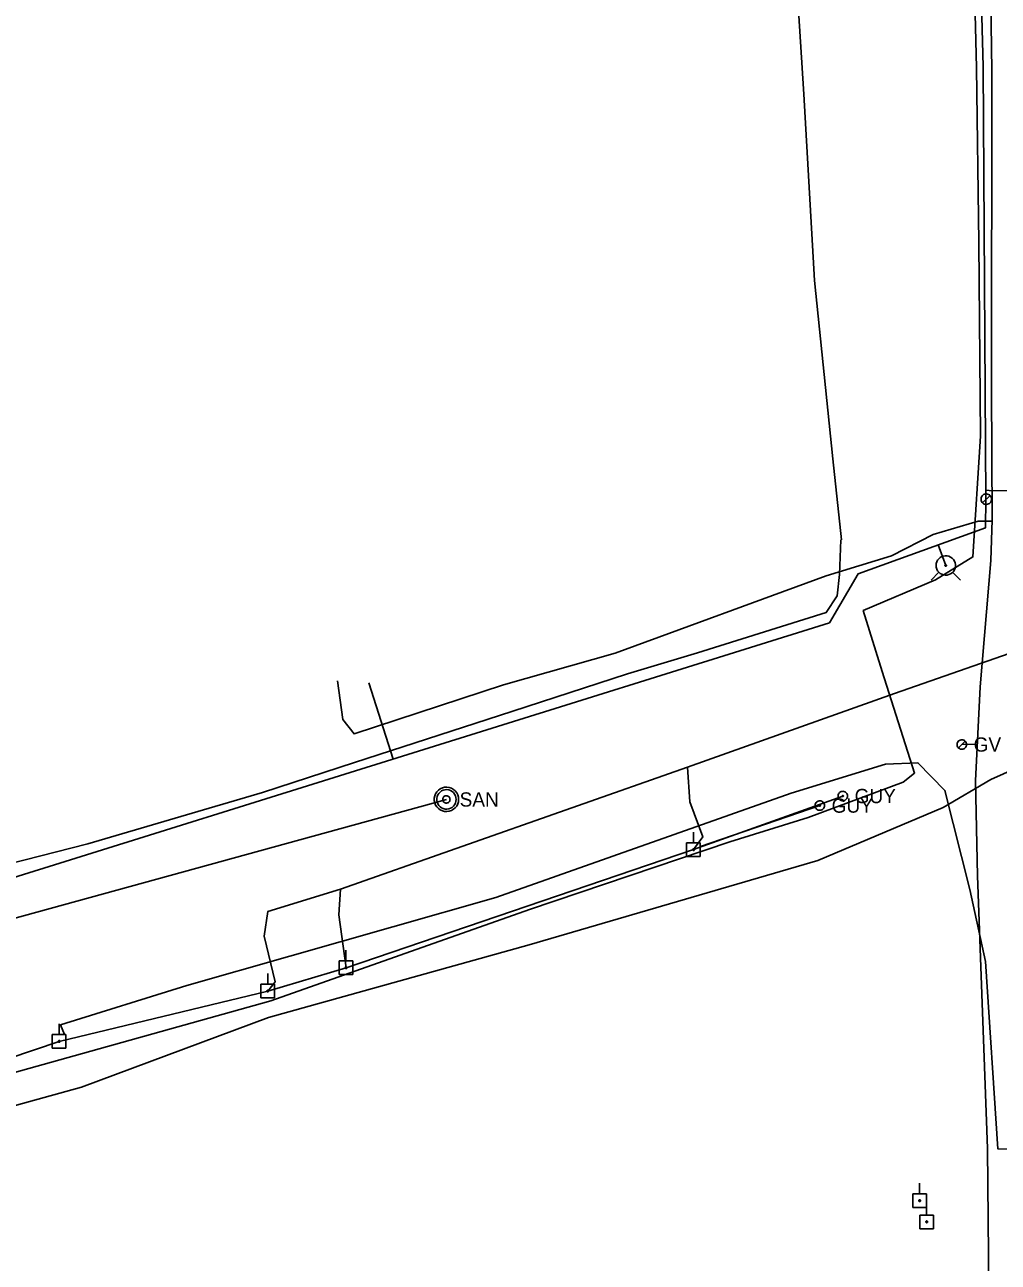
# Model space of a CAD drawing. Extents: x 600849 to 606371, y 330010 to 403088.
# Drawn here: x 604586.8 to 604850, y 333639.5 to 333973.9 of the extents above; entities that cross this region are included whole.
import ezdxf

# ---------------------------------------------------------------- set-up
doc = ezdxf.new("R2010")
doc.units = 0
for name, color, linetype in [('E_UTL_E_UG', 7, 'Continuous'), ('E_UTL_EGuyWire', 7, 'Continuous'), ('E_UTL_EPowerPole', 7, 'Continuous'), ('E_UTL_FO_UG_QWEST', 7, 'Continuous'), ('E_UTL_G', 7, 'Continuous'), ('E_UTL_G_UG', 7, 'Continuous'), ('E_UTL_Overhead', 7, 'Continuous'), ('E_UTL_SAN', 7, 'Continuous'), ('E_UTL_SAN_UG', 7, 'Continuous'), ('E_UTL_T_UG', 7, 'Continuous'), ('E_UTL_W', 7, 'Continuous'), ('E_UTL_W_UG', 7, 'Continuous'), ('E_UTL_WHydrant', 7, 'Continuous')]:
    doc.layers.add(name, color=color, linetype=linetype)

msp = doc.modelspace()

# ---------------------------------------------------------------- linework, layer by layer
at = {"layer": 'E_UTL_E_UG'}
msp.add_line((604671.71, 333733.36), (604673.7, 333719.09), dxfattribs=at)
for points in [[(604807.59, 333834.76), (604805.26, 333856.62), (604800.37, 333904.78), (604797.43, 333955.12), (604794.17, 334006.19), (604805.24, 334046.05)], [(604440.14, 333718.83), (604480.42, 333725.03), (604538.85, 333736.02), (604603.87, 333752.62), (604651.09, 333766.43), (604675.97, 333774.58), (604718.55, 333788.33), (604749.73, 333798.5), (604768.73, 333804.21), (604803.48, 333815.07), (604806.49, 333819.63), (604807.09, 333825.4), (604807.44, 333834.72)], [(604767.62, 333751), (604770.14, 333754.43), (604766.59, 333763.96), (604765.98, 333773.32), (604821.96, 333793.21), (604872.29, 333810.74)], [(604597.6, 333701.08), (604596.5, 333703.7), (604630.64, 333714.29), (604714.18, 333738.06), (604794.04, 333766.23), (604819.54, 333774.15), (604828.3, 333774.47), (604835.57, 333767), (604842.31, 333740.21), (604846.52, 333720.82)], [(604652.54, 333712.8), (604654.49, 333715.25), (604651.55, 333727.64), (604652.56, 333734.31), (604672.23, 333740.35), (604765.98, 333773.32)], [(604672.23, 333740.35), (604671.71, 333733.36)], [(604846.52, 333720.82), (604849.87, 333670.16), (604892.6, 333668.93), (604894.5, 333662.83)]]:
    msp.add_lwpolyline(points, dxfattribs=at)
at = {"layer": 'E_UTL_EGuyWire'}
for p, q in [((604807.96, 333765.49), (604767.62, 333751)), ((604801.75, 333762.91), (604769.53, 333751.88))]:
    msp.add_line(p, q, dxfattribs=at)
for points in [[(604809.24, 333765.49), (604809.22, 333765.74), (604809.15, 333765.97), (604809.04, 333766.19), (604808.89, 333766.38), (604808.7, 333766.54), (604808.49, 333766.66), (604808.26, 333766.74), (604808.02, 333766.77), (604807.78, 333766.76), (604807.54, 333766.71), (604807.32, 333766.6), (604807.12, 333766.46), (604806.95, 333766.29), (604806.82, 333766.08), (604806.73, 333765.85), (604806.68, 333765.61), (604806.68, 333765.37), (604806.73, 333765.13), (604806.82, 333764.9), (604806.95, 333764.7), (604807.12, 333764.52), (604807.32, 333764.38), (604807.54, 333764.28), (604807.78, 333764.22), (604808.02, 333764.21), (604808.26, 333764.25), (604808.49, 333764.33), (604808.7, 333764.45), (604808.89, 333764.61), (604809.04, 333764.8), (604809.15, 333765.02), (604809.22, 333765.25), (604809.24, 333765.49)], [(604808.12, 333765.49), (604808.12, 333765.52), (604808.11, 333765.55), (604808.1, 333765.58), (604808.08, 333765.6), (604808.05, 333765.62), (604808.03, 333765.64), (604808, 333765.65), (604807.97, 333765.65), (604807.94, 333765.65), (604807.91, 333765.64), (604807.88, 333765.63), (604807.86, 333765.61), (604807.83, 333765.59), (604807.82, 333765.57), (604807.81, 333765.54), (604807.8, 333765.51), (604807.8, 333765.48), (604807.81, 333765.45), (604807.82, 333765.42), (604807.83, 333765.39), (604807.86, 333765.37), (604807.88, 333765.35), (604807.91, 333765.34), (604807.94, 333765.33), (604807.97, 333765.33), (604808, 333765.34), (604808.03, 333765.35), (604808.05, 333765.36), (604808.08, 333765.38), (604808.1, 333765.41), (604808.11, 333765.43), (604808.12, 333765.46), (604808.12, 333765.49)], [(604803.03, 333762.91), (604803.01, 333763.16), (604802.94, 333763.39), (604802.83, 333763.61), (604802.68, 333763.8), (604802.49, 333763.96), (604802.28, 333764.08), (604802.05, 333764.16), (604801.81, 333764.19), (604801.57, 333764.18), (604801.33, 333764.13), (604801.11, 333764.02), (604800.91, 333763.88), (604800.74, 333763.71), (604800.61, 333763.5), (604800.52, 333763.27), (604800.47, 333763.03), (604800.47, 333762.79), (604800.52, 333762.55), (604800.61, 333762.32), (604800.74, 333762.12), (604800.91, 333761.94), (604801.11, 333761.8), (604801.33, 333761.7), (604801.57, 333761.64), (604801.81, 333761.63), (604802.05, 333761.67), (604802.28, 333761.75), (604802.49, 333761.87), (604802.68, 333762.03), (604802.83, 333762.22), (604802.94, 333762.44), (604803.01, 333762.67), (604803.03, 333762.91)], [(604801.91, 333762.91), (604801.91, 333762.94), (604801.9, 333762.97), (604801.89, 333763), (604801.87, 333763.02), (604801.84, 333763.04), (604801.82, 333763.06), (604801.79, 333763.07), (604801.76, 333763.07), (604801.73, 333763.07), (604801.7, 333763.06), (604801.67, 333763.05), (604801.65, 333763.03), (604801.62, 333763.01), (604801.61, 333762.99), (604801.6, 333762.96), (604801.59, 333762.93), (604801.59, 333762.9), (604801.6, 333762.87), (604801.61, 333762.84), (604801.62, 333762.81), (604801.65, 333762.79), (604801.67, 333762.77), (604801.7, 333762.76), (604801.73, 333762.75), (604801.76, 333762.75), (604801.79, 333762.76), (604801.82, 333762.77), (604801.84, 333762.78), (604801.87, 333762.8), (604801.89, 333762.83), (604801.9, 333762.85), (604801.91, 333762.88), (604801.91, 333762.91)]]:
    msp.add_lwpolyline(points, dxfattribs=at)
at = {"layer": 'E_UTL_EPowerPole'}
for points in [[(604767.59, 333752.84), (604767.59, 333755.75)], [(604769.43, 333752.84), (604765.74, 333752.84)], [(604765.74, 333752.84), (604765.74, 333749.15)], [(604769.43, 333749.15), (604769.43, 333752.84)], [(604765.74, 333749.15), (604769.43, 333749.15)], [(604767.86, 333751), (604767.85, 333751.04), (604767.84, 333751.09), (604767.82, 333751.13), (604767.79, 333751.16), (604767.76, 333751.19), (604767.72, 333751.22), (604767.68, 333751.23), (604767.63, 333751.24), (604767.59, 333751.24), (604767.54, 333751.22), (604767.5, 333751.21), (604767.46, 333751.18), (604767.43, 333751.15), (604767.41, 333751.11), (604767.39, 333751.07), (604767.38, 333751.02), (604767.38, 333750.98), (604767.39, 333750.93), (604767.41, 333750.89), (604767.43, 333750.85), (604767.46, 333750.82), (604767.5, 333750.79), (604767.54, 333750.77), (604767.59, 333750.76), (604767.63, 333750.76), (604767.68, 333750.77), (604767.72, 333750.78), (604767.76, 333750.81), (604767.79, 333750.83), (604767.82, 333750.87), (604767.84, 333750.91), (604767.85, 333750.95), (604767.86, 333751)], [(604673.66, 333720.93), (604673.66, 333723.84)], [(604675.51, 333720.93), (604671.82, 333720.93)], [(604671.82, 333720.93), (604671.82, 333717.24)], [(604673.94, 333719.09), (604673.93, 333719.14), (604673.92, 333719.18), (604673.9, 333719.22), (604673.87, 333719.25), (604673.84, 333719.28), (604673.8, 333719.31), (604673.75, 333719.32), (604673.71, 333719.33), (604673.66, 333719.33), (604673.62, 333719.32), (604673.58, 333719.3), (604673.54, 333719.27), (604673.51, 333719.24), (604673.48, 333719.2), (604673.47, 333719.16), (604673.46, 333719.11), (604673.46, 333719.07), (604673.47, 333719.02), (604673.48, 333718.98), (604673.51, 333718.94), (604673.54, 333718.91), (604673.58, 333718.88), (604673.62, 333718.87), (604673.66, 333718.85), (604673.71, 333718.85), (604673.75, 333718.86), (604673.8, 333718.87), (604673.84, 333718.9), (604673.87, 333718.93), (604673.9, 333718.96), (604673.92, 333719), (604673.93, 333719.05), (604673.94, 333719.09)], [(604675.51, 333717.24), (604675.51, 333720.93)], [(604652.51, 333714.65), (604652.51, 333717.56)], [(604671.82, 333717.24), (604675.51, 333717.24)], [(604654.35, 333714.65), (604650.66, 333714.65)], [(604650.66, 333714.65), (604650.66, 333710.96)], [(604652.78, 333712.8), (604652.77, 333712.85), (604652.76, 333712.89), (604652.74, 333712.93), (604652.71, 333712.97), (604652.68, 333713), (604652.64, 333713.02), (604652.59, 333713.04), (604652.55, 333713.04), (604652.5, 333713.04), (604652.46, 333713.03), (604652.42, 333713.01), (604652.38, 333712.98), (604652.35, 333712.95), (604652.33, 333712.91), (604652.31, 333712.87), (604652.3, 333712.83), (604652.3, 333712.78), (604652.31, 333712.74), (604652.33, 333712.7), (604652.35, 333712.66), (604652.38, 333712.62), (604652.42, 333712.6), (604652.46, 333712.58), (604652.5, 333712.57), (604652.55, 333712.57), (604652.59, 333712.57), (604652.64, 333712.59), (604652.68, 333712.61), (604652.71, 333712.64), (604652.74, 333712.68), (604652.76, 333712.72), (604652.77, 333712.76), (604652.78, 333712.8)], [(604654.35, 333710.96), (604654.35, 333714.65)], [(604650.66, 333710.96), (604654.35, 333710.96)], [(604596.1, 333701.04), (604596.1, 333703.94)], [(604597.95, 333701.04), (604594.26, 333701.04)], [(604594.26, 333701.04), (604594.26, 333697.34)], [(604596.38, 333699.19), (604596.37, 333699.24), (604596.36, 333699.28), (604596.34, 333699.32), (604596.31, 333699.36), (604596.28, 333699.39), (604596.24, 333699.41), (604596.19, 333699.42), (604596.15, 333699.43), (604596.1, 333699.43), (604596.06, 333699.42), (604596.02, 333699.4), (604595.98, 333699.37), (604595.95, 333699.34), (604595.92, 333699.3), (604595.91, 333699.26), (604595.9, 333699.22), (604595.9, 333699.17), (604595.91, 333699.13), (604595.92, 333699.08), (604595.95, 333699.05), (604595.98, 333699.01), (604596.02, 333698.99), (604596.06, 333698.97), (604596.1, 333698.96), (604596.15, 333698.95), (604596.19, 333698.96), (604596.24, 333698.98), (604596.28, 333699), (604596.31, 333699.03), (604596.34, 333699.06), (604596.36, 333699.1), (604596.37, 333699.15), (604596.38, 333699.19)], [(604597.95, 333697.34), (604597.95, 333701.04)], [(604594.26, 333697.34), (604597.95, 333697.34)], [(604830.56, 333657.97), (604826.87, 333657.97)], [(604826.87, 333657.97), (604826.87, 333654.27)], [(604828.72, 333657.97), (604828.72, 333660.87)], [(604830.56, 333654.27), (604830.56, 333657.97)], [(604828.99, 333656.12), (604828.98, 333656.17), (604828.97, 333656.21), (604828.95, 333656.25), (604828.92, 333656.29), (604828.89, 333656.32), (604828.85, 333656.34), (604828.81, 333656.35), (604828.76, 333656.36), (604828.72, 333656.36), (604828.67, 333656.35), (604828.63, 333656.33), (604828.59, 333656.3), (604828.56, 333656.27), (604828.54, 333656.23), (604828.52, 333656.19), (604828.51, 333656.15), (604828.51, 333656.1), (604828.52, 333656.06), (604828.54, 333656.01), (604828.56, 333655.98), (604828.59, 333655.94), (604828.63, 333655.92), (604828.67, 333655.9), (604828.72, 333655.89), (604828.76, 333655.88), (604828.81, 333655.89), (604828.85, 333655.91), (604828.89, 333655.93), (604828.92, 333655.96), (604828.95, 333655.99), (604828.97, 333656.03), (604828.98, 333656.08), (604828.99, 333656.12)], [(604830.64, 333652.27), (604830.64, 333655.17)], [(604826.87, 333654.27), (604830.56, 333654.27)], [(604832.48, 333652.27), (604828.79, 333652.27)], [(604828.79, 333652.27), (604828.79, 333648.57)], [(604832.48, 333648.57), (604832.48, 333652.27)], [(604828.79, 333648.57), (604832.48, 333648.57)], [(604830.91, 333650.42), (604830.9, 333650.47), (604830.89, 333650.51), (604830.87, 333650.55), (604830.84, 333650.59), (604830.81, 333650.62), (604830.77, 333650.64), (604830.73, 333650.65), (604830.68, 333650.66), (604830.64, 333650.66), (604830.59, 333650.65), (604830.55, 333650.63), (604830.51, 333650.6), (604830.48, 333650.57), (604830.46, 333650.53), (604830.44, 333650.49), (604830.43, 333650.45), (604830.43, 333650.4), (604830.44, 333650.36), (604830.46, 333650.31), (604830.48, 333650.28), (604830.51, 333650.24), (604830.55, 333650.22), (604830.59, 333650.2), (604830.64, 333650.19), (604830.68, 333650.18), (604830.73, 333650.19), (604830.77, 333650.21), (604830.81, 333650.23), (604830.84, 333650.26), (604830.87, 333650.29), (604830.89, 333650.33), (604830.9, 333650.38), (604830.91, 333650.42)]]:
    msp.add_lwpolyline(points, dxfattribs=at)
at = {"layer": 'E_UTL_FO_UG_QWEST'}
msp.add_lwpolyline([(604064.36, 333597.95), (604125.52, 333607.24), (604222.69, 333622.89), (604294.58, 333635.82), (604348.76, 333642.01), (604429.81, 333649.86), (604519.71, 333664), (604602.19, 333686.85), (604652.71, 333705.68), (604723.21, 333725.29), (604801.25, 333748.09), (604835.09, 333762.42), (604848.03, 333769.94), (604883.85, 333785.99), (604890.17, 333789.47), (604890.94, 333790.11), (604892.16, 333796.08), (604892.06, 333804.65), (604893.55, 333818.96), (604893.11, 333877.27), (604889.73, 333952.96), (604886.58, 334030.08), (604884.67, 334105.68), (604880.28, 334183.13)], dxfattribs=at)
at = {"layer": 'E_UTL_G'}
for points in [[(604841.41, 333779.41), (604841.39, 333779.66), (604841.32, 333779.89), (604841.21, 333780.11), (604841.06, 333780.3), (604840.87, 333780.46), (604840.66, 333780.58), (604840.43, 333780.66), (604840.19, 333780.69), (604839.95, 333780.68), (604839.71, 333780.63), (604839.49, 333780.52), (604839.29, 333780.38), (604839.12, 333780.21), (604838.99, 333780), (604838.9, 333779.77), (604838.85, 333779.53), (604838.85, 333779.29), (604838.9, 333779.05), (604838.99, 333778.82), (604839.12, 333778.62), (604839.29, 333778.44), (604839.49, 333778.3), (604839.71, 333778.2), (604839.95, 333778.14), (604840.19, 333778.13), (604840.43, 333778.17), (604840.66, 333778.25), (604840.87, 333778.37), (604841.06, 333778.53), (604841.21, 333778.72), (604841.32, 333778.94), (604841.39, 333779.17), (604841.41, 333779.41)], [(604839.22, 333778.51), (604841.04, 333780.32)]]:
    msp.add_lwpolyline(points, dxfattribs=at)
at = {"layer": 'E_UTL_G_UG'}
for points in [[(604845.08, 333795.02), (604847.97, 333829.11), (604848.35, 333840.17), (604848.14, 333875.54), (604848.22, 333961.6), (604847.47, 334017.45), (604847.16, 334022.52)], [(604716.26, 333795.51), (604746.45, 333804.07), (604803.5, 333825.03), (604821.12, 333830.43), (604832.44, 333836.15), (604844.53, 333839.78), (604848.34, 333839.76)], [(604671.41, 333796.64), (604672.81, 333786.15), (604675.87, 333782.29), (604716.26, 333795.51)], [(604803.13, 333062.75), (604804.47, 333067.46), (604804.82, 333068.5), (604814.84, 333081.84), (604828.52, 333091.01), (604836.1, 333095.96), (604841.81, 333158.17), (604844.49, 333210.93), (604845.82, 333274.99), (604846.65, 333319.21), (604847.29, 333342.28), (604849.65, 333436.7), (604848.05, 333522.17), (604847.68, 333603.32), (604847.05, 333670.25), (604844.38, 333743.96), (604843.81, 333769.64), (604845.08, 333795.02)], [(604840.13, 333779.45), (604844.31, 333779.49)]]:
    msp.add_lwpolyline(points, dxfattribs=at)
at = {"layer": 'E_UTL_Overhead'}
msp.add_lwpolyline([(604011.76, 333675.14), (604171.63, 333672.92), (604269.99, 333669.95), (604431.16, 333658.05), (604568.86, 333689.94), (604596.14, 333699.19), (604652.54, 333712.8), (604673.7, 333719.09), (604767.62, 333751)], dxfattribs=at)
at = {"layer": 'E_UTL_SAN'}
for points in [[(604704.12, 333764.58), (604704.06, 333765.21), (604703.89, 333765.81), (604703.6, 333766.37), (604703.21, 333766.86), (604702.74, 333767.27), (604702.19, 333767.59), (604701.6, 333767.79), (604700.98, 333767.88), (604700.35, 333767.85), (604699.74, 333767.7), (604699.17, 333767.44), (604698.66, 333767.08), (604698.23, 333766.62), (604697.89, 333766.1), (604697.66, 333765.51), (604697.54, 333764.9), (604697.54, 333764.27), (604697.66, 333763.65), (604697.89, 333763.07), (604698.23, 333762.54), (604698.66, 333762.09), (604699.17, 333761.73), (604699.74, 333761.47), (604700.35, 333761.32), (604700.98, 333761.29), (604701.6, 333761.38), (604702.19, 333761.58), (604702.74, 333761.9), (604703.21, 333762.31), (604703.6, 333762.8), (604703.89, 333763.36), (604704.06, 333763.96), (604704.12, 333764.58)], [(604703.46, 333764.58), (604703.41, 333765.08), (604703.27, 333765.56), (604703.04, 333766.01), (604702.73, 333766.41), (604702.35, 333766.73), (604701.92, 333766.99), (604701.44, 333767.15), (604700.95, 333767.22), (604700.45, 333767.2), (604699.96, 333767.08), (604699.5, 333766.87), (604699.09, 333766.58), (604698.75, 333766.22), (604698.48, 333765.79), (604698.29, 333765.33), (604698.19, 333764.83), (604698.19, 333764.33), (604698.29, 333763.84), (604698.48, 333763.37), (604698.75, 333762.95), (604699.09, 333762.59), (604699.5, 333762.3), (604699.96, 333762.09), (604700.45, 333761.97), (604700.95, 333761.95), (604701.44, 333762.02), (604701.92, 333762.18), (604702.35, 333762.43), (604702.73, 333762.76), (604703.04, 333763.16), (604703.27, 333763.6), (604703.41, 333764.08), (604703.46, 333764.58)], [(604701.81, 333764.58), (604701.79, 333764.77), (604701.74, 333764.95), (604701.66, 333765.12), (604701.54, 333765.27), (604701.4, 333765.39), (604701.23, 333765.48), (604701.06, 333765.55), (604700.87, 333765.57), (604700.68, 333765.56), (604700.5, 333765.52), (604700.33, 333765.44), (604700.17, 333765.33), (604700.04, 333765.2), (604699.94, 333765.04), (604699.87, 333764.86), (604699.84, 333764.68), (604699.84, 333764.49), (604699.87, 333764.3), (604699.94, 333764.13), (604700.04, 333763.97), (604700.17, 333763.84), (604700.33, 333763.73), (604700.5, 333763.65), (604700.68, 333763.6), (604700.87, 333763.59), (604701.06, 333763.62), (604701.23, 333763.68), (604701.4, 333763.78), (604701.54, 333763.9), (604701.66, 333764.05), (604701.74, 333764.22), (604701.79, 333764.4), (604701.81, 333764.58)]]:
    msp.add_lwpolyline(points, dxfattribs=at)
at = {"layer": 'E_UTL_SAN_UG'}
msp.add_line((604507.11, 333711.32), (604700.82, 333764.58), dxfattribs=at)
at = {"layer": 'E_UTL_T_UG'}
msp.add_lwpolyline([(604287.56, 333667.46), (604321.18, 333666.93), (604440.94, 333666.46), (604493.47, 333670.08), (604529.7, 333676.11), (604555.97, 333682.92), (604653.39, 333710.18), (604723.28, 333734.82), (604777.43, 333753.12), (604798.61, 333759.72), (604824.33, 333769.22), (604827.36, 333771.7), (604818.65, 333799.13), (604813.51, 333815.63), (604833.03, 333823.91), (604843.16, 333830.13), (604845.18, 333862.78), (604844.73, 333915.07), (604844.08, 333962.32), (604842.41, 334031.55)], dxfattribs=at)
at = {"layer": 'E_UTL_W'}
for points in [[(604848.19, 333845.72), (604848.16, 333845.99), (604848.08, 333846.25), (604847.96, 333846.49), (604847.79, 333846.71), (604847.59, 333846.88), (604847.35, 333847.02), (604847.1, 333847.11), (604846.83, 333847.15), (604846.56, 333847.13), (604846.29, 333847.07), (604846.05, 333846.96), (604845.83, 333846.8), (604845.64, 333846.6), (604845.49, 333846.38), (604845.39, 333846.12), (604845.34, 333845.86), (604845.34, 333845.59), (604845.39, 333845.32), (604845.49, 333845.07), (604845.64, 333844.84), (604845.83, 333844.64), (604846.05, 333844.49), (604846.29, 333844.37), (604846.56, 333844.31), (604846.83, 333844.3), (604847.1, 333844.34), (604847.35, 333844.43), (604847.59, 333844.56), (604847.79, 333844.74), (604847.96, 333844.95), (604848.08, 333845.19), (604848.16, 333845.45), (604848.19, 333845.72)], [(604845.75, 333844.71), (604847.77, 333846.73)]]:
    msp.add_lwpolyline(points, dxfattribs=at)
at = {"layer": 'E_UTL_W_UG'}
for p, q in [((604833.79, 333833.39), (604835.81, 333827.79)), ((604543.79, 333730.94), (604804.41, 333812.32)), ((604686.46, 333775.49), (604679.83, 333796.1))]:
    msp.add_line(p, q, dxfattribs=at)
for points in [[(604846.62, 333845.73), (604845.91, 333962.63), (604845.14, 333993.13), (604845.77, 334042.88), (604845.13, 334077.17), (604842.87, 334162.23), (604837.44, 334211.69), (604837.01, 334265.02), (604832.72, 334352.02), (604829.86, 334407.8), (604827.89, 334453.7), (604825.43, 334498.81), (604822.75, 334554.4), (604821.56, 334581.06), (604817.29, 334667.8), (604815.06, 334708.63), (604813.04, 334742.82), (604812.12, 334767.3), (604810.04, 334815.66), (604808.35, 334858.79), (604805.32, 334921.82), (604804.92, 334936.69), (604802.65, 334960.89), (604797.31, 335097.75)], [(604846.59, 333848.17), (604847.55, 333848.09), (604879.58, 333847.97), (604889.65, 333848.11), (605000.07, 333859.97), (605001.26, 333860.06), (605020.88, 333861.59), (605022.55, 333861.68)], [(604804.41, 333812.32), (604812.16, 333825.57), (604846.56, 333838), (604846.6, 333845.73)]]:
    msp.add_lwpolyline(points, dxfattribs=at)
at = {"layer": 'E_UTL_WHydrant'}
for points in [[(604833.18, 333827.8), (604833.23, 333827.31), (604833.37, 333826.83), (604833.59, 333826.38), (604833.9, 333825.99), (604834.28, 333825.67), (604834.71, 333825.42), (604835.18, 333825.25), (604835.68, 333825.18), (604836.17, 333825.21), (604836.66, 333825.32), (604837.11, 333825.53), (604837.52, 333825.82), (604837.86, 333826.18), (604838.13, 333826.6), (604838.32, 333827.06), (604838.41, 333827.55), (604838.41, 333828.05), (604838.32, 333828.54), (604838.13, 333829), (604837.86, 333829.42), (604837.52, 333829.78), (604837.11, 333830.07), (604836.66, 333830.28), (604836.17, 333830.4), (604835.68, 333830.42), (604835.18, 333830.35), (604834.71, 333830.19), (604834.28, 333829.94), (604833.9, 333829.61), (604833.59, 333829.22), (604833.37, 333828.78), (604833.23, 333828.3), (604833.18, 333827.8)], [(604833.96, 333825.97), (604831.82, 333823.82)], [(604835.6, 333827.8), (604835.6, 333827.76), (604835.61, 333827.73), (604835.63, 333827.69), (604835.66, 333827.66), (604835.68, 333827.64), (604835.72, 333827.62), (604835.75, 333827.61), (604835.79, 333827.6), (604835.83, 333827.6), (604835.87, 333827.61), (604835.9, 333827.63), (604835.93, 333827.65), (604835.96, 333827.68), (604835.98, 333827.71), (604835.99, 333827.75), (604836, 333827.78), (604836, 333827.82), (604835.99, 333827.86), (604835.98, 333827.89), (604835.96, 333827.93), (604835.93, 333827.95), (604835.9, 333827.98), (604835.87, 333827.99), (604835.83, 333828), (604835.79, 333828), (604835.75, 333828), (604835.72, 333827.98), (604835.68, 333827.97), (604835.66, 333827.94), (604835.63, 333827.91), (604835.61, 333827.88), (604835.6, 333827.84), (604835.6, 333827.8)], [(604837.63, 333825.97), (604839.78, 333823.82)]]:
    msp.add_lwpolyline(points, dxfattribs=at)

# ---------------------------------------------------------------- texts
at = {"layer": 'E_UTL_EGuyWire'}
for p in [(604811.17, 333763.57), (604804.96, 333760.99)]:
    msp.add_text('GUY', height=3.85, dxfattribs=at).set_placement(p)
at = {"layer": 'E_UTL_G'}
msp.add_text('GV', height=3.85, dxfattribs=at).set_placement((604843.34, 333777.49))
at = {"layer": 'E_UTL_SAN'}
msp.add_text('SAN', height=3.849, dxfattribs=at).set_placement((604704.39, 333762.64))

doc.saveas('drawing.dxf')
